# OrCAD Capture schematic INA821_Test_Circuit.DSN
size A; title: INA821 35-µV Offset, 7-nV/vHz Noise, Low-Power; rev: 1.1; note: Datasheet: SBOS893D  EVM: N/A
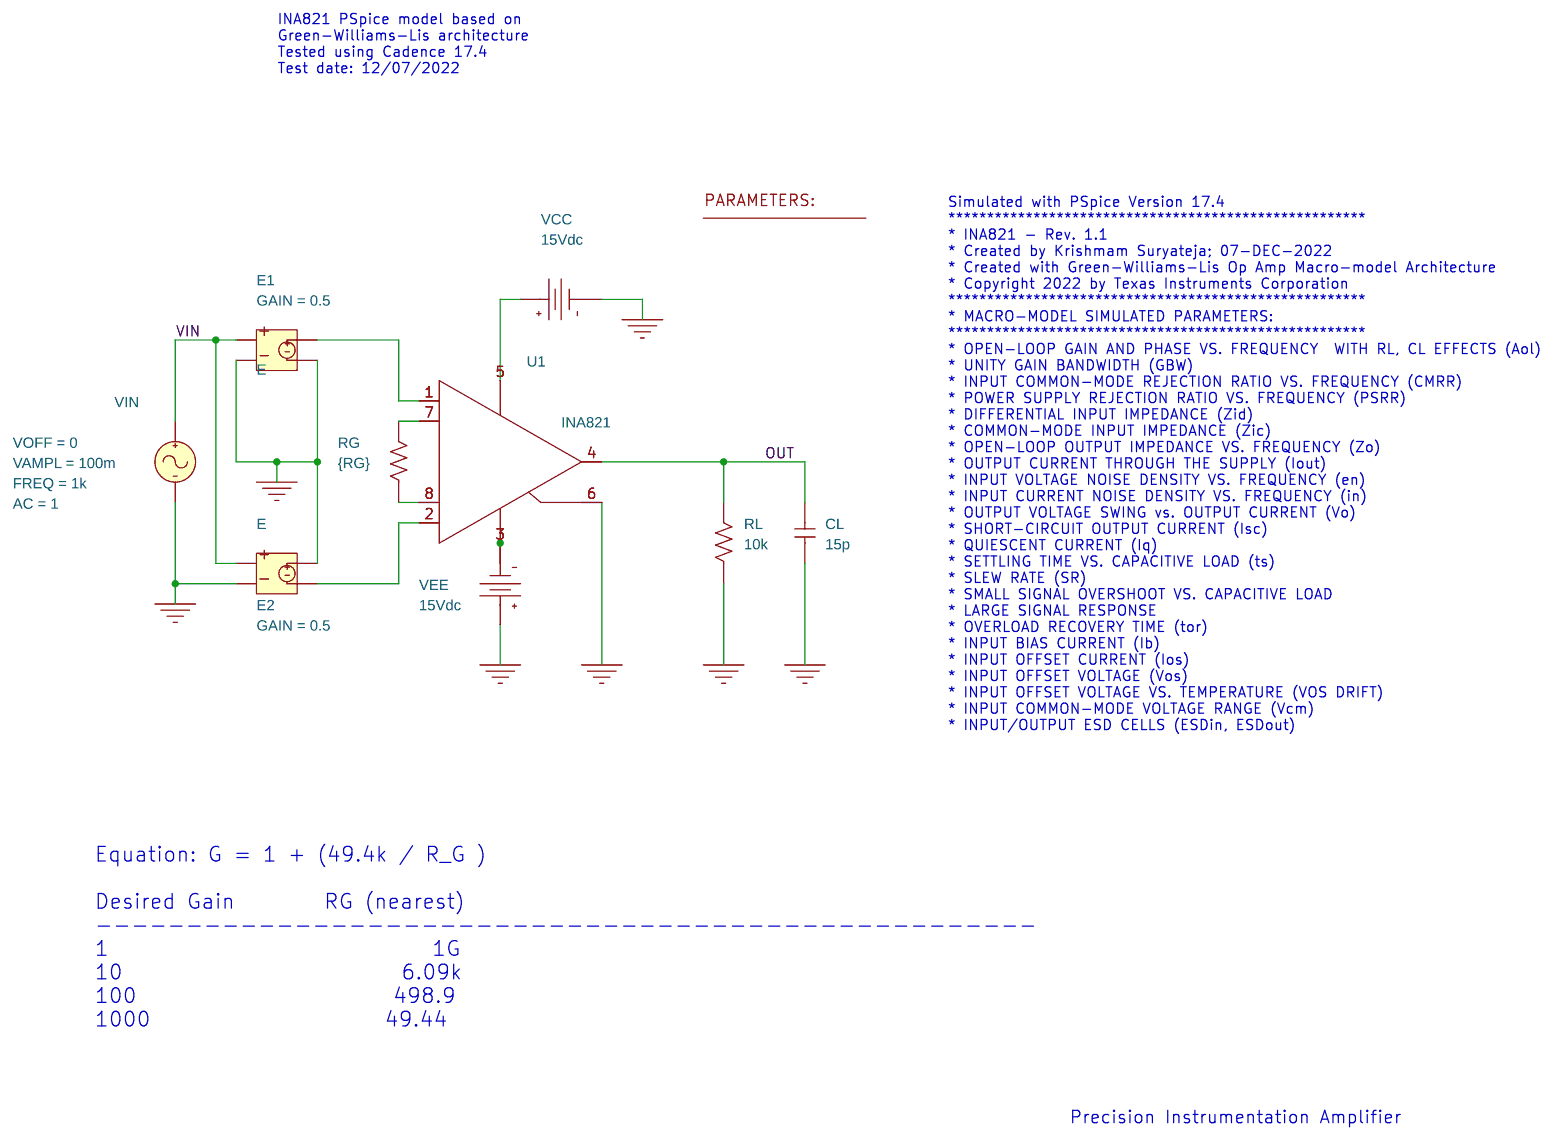
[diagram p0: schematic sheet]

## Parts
1  PARAM
CL  15p  [RAD/CK05]
E1  E
E2  E
RG  {RG}  [AX/RC05]
RL  10k  [AX/RC05]
U1  INA821
VCC  VDC
VEE  VDC
VIN  VSIN

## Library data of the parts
1 = PARAM: RG: 1G
CL = C
E1 E2 = E: GAIN: 0.5
RG RL = R
U1 = INA821
VCC VEE = VDC: DC: 15Vdc
VIN = VSIN: AC: 1; FREQ: 1k; VAMPL: 100m; VOFF: 0

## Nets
VIN: E1.1 E2.1 VIN.1(+)
0: CL.1 E1.2 E1.4 E2.2 E2.3 RL.1 U1.6(REF) VCC.1(-) VEE.0(+) VIN.2(-)
OUT: CL.2 RL.2 U1.4(OUT)
N11906: U1.5(V+) VCC.0(+)
N12164: E1.3 U1.1(+)
N12256: E2.4 U1.2(-)
N12274: RG.2 U1.7(RG+)
N12280: RG.1 U1.8(RG-)
N12296: U1.3(V-) VEE.1(-)

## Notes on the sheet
- INA821 PSpice model based on
  Green-Williams-Lis architecture
  Tested using Cadence 17.4
  Test date: 12/07/2022
- Simulated with PSpice Version 17.4
  ******************************************************
  * INA821 - Rev. 1.1
  * Created by Krishmam Suryateja; 07-DEC-2022
  * Created with Green-Williams-Lis Op Amp Macro-model Architecture
  * Copyright 2022 by Texas Instruments Corporation
  ******************************************************
  * MACRO-MODEL SIMULATED PARAMETERS:
  ******************************************************
  * OPEN-LOOP GAIN AND PHASE VS. FREQUENCY  WITH RL, CL EFFECTS (Aol)
  * UNITY GAIN BANDWIDTH (GBW)
  * INPUT COMMON-MODE REJECTION RATIO VS. FREQUENCY (CMRR)
  * POWER SUPPLY REJECTION RATIO VS. FREQUENCY (PSRR)
  * DIFFERENTIAL INPUT IMPEDANCE (Zid)
  * COMMON-MODE INPUT IMPEDANCE (Zic)
  * OPEN-LOOP OUTPUT IMPEDANCE VS. FREQUENCY (Zo)
  * OUTPUT CURRENT THROUGH THE SUPPLY (Iout)
  * INPUT VOLTAGE NOISE DENSITY VS. FREQUENCY (en)
  * INPUT CURRENT NOISE DENSITY VS. FREQUENCY (in)
  * OUTPUT VOLTAGE SWING vs. OUTPUT CURRENT (Vo)
  * SHORT-CIRCUIT OUTPUT CURRENT (Isc)
  * QUIESCENT CURRENT (Iq)
  * SETTLING TIME VS. CAPACITIVE LOAD (ts)
  * SLEW RATE (SR)
  * SMALL SIGNAL OVERSHOOT VS. CAPACITIVE LOAD
  * LARGE SIGNAL RESPONSE
  * OVERLOAD RECOVERY TIME (tor)
  * INPUT BIAS CURRENT (Ib)
  * INPUT OFFSET CURRENT (Ios)
  * INPUT OFFSET VOLTAGE (Vos)
  * INPUT OFFSET VOLTAGE VS. TEMPERATURE (VOS DRIFT)
  * INPUT COMMON-MODE VOLTAGE RANGE (Vcm)
  * INPUT/OUTPUT ESD CELLS (ESDin, ESDout)
- Equation: G = 1 + (49.4k / R_G )
  Desired Gain        RG (nearest)
  ----------------------------------------------------
  1                             1G
  10                         6.09k
  100                       498.9
  1000                     49.44
- Precision Instrumentation Amplifier
